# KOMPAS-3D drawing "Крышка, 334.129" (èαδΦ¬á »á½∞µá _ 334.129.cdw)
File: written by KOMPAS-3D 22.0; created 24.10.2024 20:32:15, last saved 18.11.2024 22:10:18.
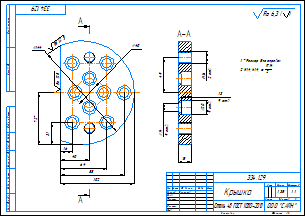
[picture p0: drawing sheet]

Sheet 1: A3, landscape

Document properties: Автор: aleksander.larionov.10@gmail.com; Полное имя файла: C:\Мои папки\Работа\Крышки, фланцы\334.129\Крышка пальца _ 334.129.cdw; Знак неуказанной шероховатости: 4; Параметр неуказанной шероховатости: Ra 6,3; Масса: 1.350551

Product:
- Part/product: Крышка  | designation 334.129
    Материал: Сталь 45 ГОСТ 1050-2013 (density 7810 kg/m3)
    Масса: 1.350551

Title block, sheet 1: Наименование: Крышка; designation: 334.129; Материал: Сталь 45 ГОСТ 1050-2013; Масса: 1,35; Количество листов документа: 1; organisation: ООО "САЙН"; Форматы листов документа: A3; stored path: C:\Users\aleks\Desktop\Работа\334.129PQ\Шайба _ 334.129PQ.cdw; Разработал: Ларионов

Views: Вид 1, Сверху, Разрез А-А
Referenced files in C:\Users\aleks\Desktop\Работа\334.129PQ\: Крышка пальца _ 334.129PQ.m3d
Referenced files in C:\Users\aleks\Desktop\Работа\334.129\: Крышка пальца _ 334.129.m3d
Referenced files in C:\Мои папки\Работа\Крышки, фланцы\334.129\: Крышка пальца _ 334.129.m3d
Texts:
  Ra 12,5
  Ra 6,3
  Ra 6,3 ( )
Dimensions and other numbers on the sheet: 144; 16; 40; 64; 88; 102; 72; 31; 1  Размер для справок.; 2 H14, h14,    IT14 2 .; 1; 334.129; 20; 9 отв.; 14; 18; 13; 2 отв.; 49; 1:1; 1,35; 334.129 Крышка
